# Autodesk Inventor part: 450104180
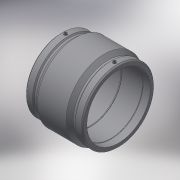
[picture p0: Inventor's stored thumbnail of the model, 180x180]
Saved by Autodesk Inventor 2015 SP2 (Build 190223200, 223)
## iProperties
Created: 2017-06
Part Number: 450104180
Material: Generic
Description: PLASSON COUPLER 180 PN25
Document SubType Name: Modeling
Designer: KIM
Mass: 8622.19 g
Surface Area: 6772.47 cm^2
Volume: 8622.19 cm^3
Density: 1 g/cm^3
Appearance: Default
Author: KIM
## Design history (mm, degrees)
derived "450104.ipt"
feature "Solid1::450104.ipt"
tag "TaggingFeature1"
body "Solid1"
other parameters: "d0" = 212, "d2" = 224, "d3" = 104, "d4" = 53, "d5" = 201.6, "d6" = 144, "d8" = 168 deg, "d10" = 41.6, "d11" = 13.86667, "d13" = 212, "d14" = 17.6296, "d15" = 104, "d16" = 104, "d17" = 178.2, "d19" = 3.52592, "d20" = 168 deg, "d22" = 210.56, "d23" = 224, "d24" = 204.2432, "d25" = 135 deg, "d26" = 106, "d27" = 135 deg, "d29" = 114, "d30" = 15, "d31" = 74.2, "d34" = 5 deg, "d35" = 15, "d39" = 5 deg, "d41" = 4, "d42" = 14, "d43" = 0, "d45" = 4, "d46" = 14, "d47" = 0, "d48" = 3, "d49" = 0, "d50" = 3, "d51" = 0, "d52" = 30.16, "d53" = 7.54, "L_" = 212, "L_1" = 104, "D_" = 224, "A_" = 114, "d_2" = 12
